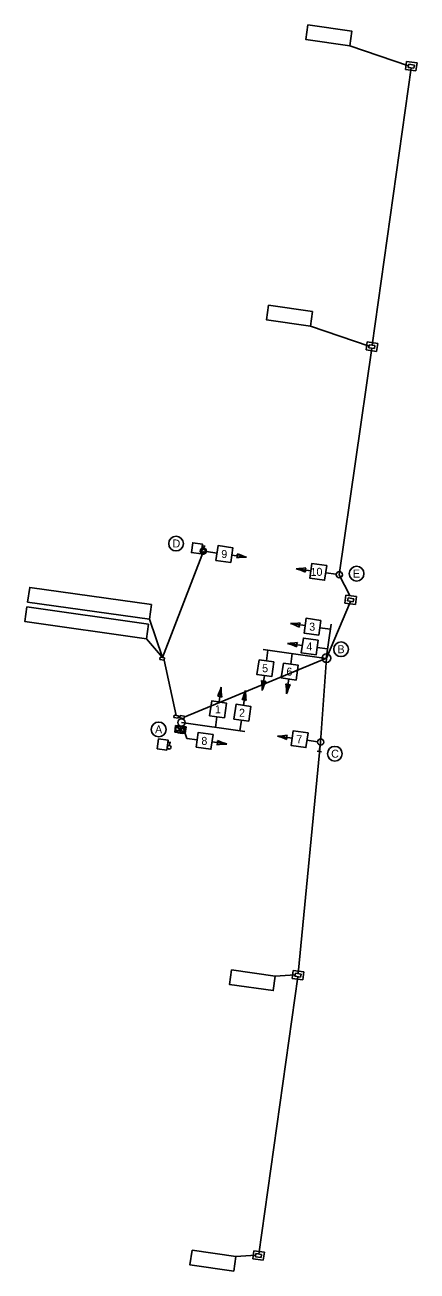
# Model space of a CAD drawing. Extents: x 993729 to 994927, y 1984823 to 1986420.
# Drawn here: x 993729 to 993889, y 1985201 to 1985707 of the extents above; entities that cross this region are included whole.
import ezdxf

# ---------------------------------------------------------------- set-up
doc = ezdxf.new("R2010")
doc.units = 0
for name, color, linetype in [('EX_BREAKLINE_PT_SYM', 7, 'Continuous'), ('EX_FLAG_POLE', 7, 'Continuous'), ('EX_GAS_UTILITIES', 7, 'Continuous'), ('EX_LANDSCAPING', 7, 'Continuous'), ('EX_MSC_PT_SYM', 7, 'Continuous'), ('EX_SANITARY_SEWER', 7, 'Continuous'), ('EX_UTILITY_MARKER', 7, 'Continuous')]:
    doc.layers.add(name, color=color, linetype=linetype)

msp = doc.modelspace()

# ---------------------------------------------------------------- linework, layer by layer
at = {"layer": 'EX_BREAKLINE_PT_SYM'}
for p, q in [((993802.89, 1985493.48), (993807.19, 1985492.87)), ((993813.2, 1985492.06), (993819.18, 1985491.22)), ((993845.41, 1985485.66), (993839.43, 1985486.49)), ((993855.72, 1985484.24), (993851.42, 1985484.84)), ((993843.03, 1985463.38), (993837.05, 1985464.23)), ((993853.34, 1985461.94), (993849.04, 1985462.55)), ((993841.9, 1985455.34), (993835.92, 1985456.19)), ((993827.91, 1985453.4), (993827.29, 1985449.1)), ((993837.81, 1985452.03), (993837.2, 1985447.72)), ((993852.21, 1985453.9), (993847.91, 1985454.51)), ((993826.46, 1985443.09), (993825.62, 1985437.11)), ((993836.37, 1985441.72), (993835.52, 1985435.74)), ((993808.02, 1985432.39), (993808.87, 1985438.37)), ((993817.93, 1985431.01), (993818.77, 1985436.99)), ((993806.58, 1985422.08), (993807.19, 1985426.38)), ((993794.87, 1985417.61), (993793.27, 1985422.38)), ((993816.48, 1985420.7), (993817.1, 1985425.01)), ((993794.87, 1985417.61), (993799.17, 1985417)), ((993805.18, 1985416.17), (993811.16, 1985415.32)), ((993837.8, 1985417.69), (993831.82, 1985418.54)), ((993848.11, 1985416.25), (993843.81, 1985416.86))]:
    msp.add_line(p, q, dxfattribs=at)
for points in [[(993806.77, 1985489.89), (993807.61, 1985495.89), (993813.62, 1985495.05), (993812.78, 1985489.05)], [(993851.84, 1985487.83), (993850.99, 1985481.82), (993844.99, 1985482.66), (993845.83, 1985488.67)], [(993849.46, 1985465.54), (993848.61, 1985459.54), (993842.61, 1985460.39), (993843.46, 1985466.39)], [(993848.33, 1985457.49), (993847.48, 1985451.49), (993841.48, 1985452.34), (993842.33, 1985458.35)], [(993824.31, 1985449.52), (993830.31, 1985448.67), (993829.46, 1985442.67), (993823.45, 1985443.52)], [(993834.21, 1985448.15), (993840.22, 1985447.29), (993839.36, 1985441.29), (993833.36, 1985442.14)], [(993810.18, 1985425.96), (993804.17, 1985426.81), (993805.03, 1985432.81), (993811.03, 1985431.96)], [(993820.08, 1985424.58), (993814.08, 1985425.43), (993814.93, 1985431.44), (993820.94, 1985430.58)], [(993844.23, 1985419.85), (993843.38, 1985413.84), (993837.38, 1985414.69), (993838.23, 1985420.7)], [(993798.75, 1985414.01), (993799.6, 1985420.02), (993805.6, 1985419.17), (993804.75, 1985413.16)]]:
    msp.add_lwpolyline(points, close=True, dxfattribs=at)
for centre, radius, start, end in [((993813.97, 1985491.95), 1.63, 320.1833, 23.8779), ((993827.59, 1985519.47), 29.47, 245.6842, 253.4223), ((993819.51, 1985461.75), 29.47, 90.6389, 98.377), ((993839.1, 1985515.97), 29.47, 270.6389, 278.377), ((993831.02, 1985458.25), 29.47, 65.6842, 73.4223), ((993844.64, 1985485.76), 1.63, 140.1833, 203.8779), ((993836.78, 1985493.7), 29.47, 270.5231, 278.2612), ((993828.59, 1985436), 29.47, 65.5684, 73.3065), ((993842.27, 1985463.49), 1.63, 140.0675, 203.7621), ((993835.65, 1985485.66), 29.47, 270.5231, 278.2612), ((993827.45, 1985427.96), 29.47, 65.5684, 73.3065), ((993841.13, 1985455.45), 1.63, 140.0675, 203.7621), ((993796.14, 1985436.84), 29.47, 0.5231, 8.2612), ((993826.36, 1985442.33), 1.63, 230.0675, 293.7621), ((993780.64, 1985446.83), 29.47, 335.5684, 343.3065), ((993838.34, 1985438.64), 29.47, 180.5231, 188.2612), ((993790.55, 1985445.46), 29.47, 335.5684, 343.3065), ((993848.25, 1985437.26), 29.47, 180.5231, 188.2612), ((993853.84, 1985428.65), 29.47, 155.5684, 163.3065), ((993806.05, 1985435.47), 29.47, 0.5231, 8.2612), ((993836.26, 1985440.95), 1.63, 230.0675, 293.7621), ((993863.75, 1985427.27), 29.47, 155.5684, 163.3065), ((993808.13, 1985433.15), 1.63, 50.0675, 113.7621), ((993818.03, 1985431.78), 1.63, 50.0675, 113.7621), ((993805.94, 1985416.06), 1.63, 320.0649, 23.7595), ((993819.62, 1985443.55), 29.47, 245.5658, 253.3039), ((993831.55, 1985448.01), 29.47, 270.5289, 278.267), ((993823.36, 1985390.31), 29.47, 65.5741, 73.3122), ((993837.04, 1985417.8), 1.63, 140.0732, 203.7679), ((993811.42, 1985385.85), 29.47, 90.5205, 98.2586)]:
    msp.add_arc(centre, radius, start, end, dxfattribs=at)
at = {"layer": 'EX_FLAG_POLE'}
for p, q in [((993861.19, 1985698.9), (993885.08, 1985690.75)), ((993870.31, 1985577.33), (993886.15, 1985689.95)), ((993845.18, 1985585.02), (993869.07, 1985576.87)), ((993870.13, 1985576.07), (993856.96, 1985484.06)), ((993801.65, 1985493.65), (993784.98, 1985450.43)), ((993861.3, 1985475.56), (993856.96, 1985484.06)), ((993851.69, 1985450.18), (993861.48, 1985473.24)), ((993779.67, 1985466.01), (993784.98, 1985450.43)), ((993778.55, 1985458.09), (993784.98, 1985450.43)), ((993785.71, 1985449.4), (993790.65, 1985426.89)), ((993793.86, 1985426.18), (993851.69, 1985450.18)), ((993851.69, 1985450.18), (993849.35, 1985416.07)), ((993849.35, 1985416.07), (993840.22, 1985322.07)), ((993840.04, 1985320.81), (993824.21, 1985208.19)), ((993830.88, 1985321.09), (993838.98, 1985321.6)), ((993814.87, 1985207.21), (993822.96, 1985207.72))]:
    msp.add_line(p, q, dxfattribs=at)
at = {"layer": 'EX_GAS_UTILITIES'}
for points in [[(993800.73, 1985492.52), (993796.77, 1985493.07), (993797.33, 1985497.03), (993801.29, 1985496.48)], [(993786.82, 1985412.85), (993782.86, 1985413.4), (993783.42, 1985417.36), (993787.38, 1985416.81)]]:
    msp.add_lwpolyline(points, close=True, dxfattribs=at)
at = {"layer": 'EX_LANDSCAPING'}
for p, q in [((993883.86, 1985689.27), (993884.32, 1985692.5)), ((993888.15, 1985688.66), (993883.86, 1985689.27)), ((993884.32, 1985692.5), (993888.61, 1985691.9)), ((993884.99, 1985690.12), (993885.17, 1985691.37)), ((993887.3, 1985689.79), (993884.99, 1985690.12)), ((993885.17, 1985691.37), (993887.48, 1985691.05)), ((993887.48, 1985691.05), (993887.3, 1985689.79)), ((993888.61, 1985691.9), (993888.15, 1985688.66)), ((993867.85, 1985575.39), (993868.3, 1985578.62)), ((993868.3, 1985578.62), (993872.59, 1985578.02)), ((993868.98, 1985576.24), (993869.15, 1985577.49)), ((993869.15, 1985577.49), (993871.46, 1985577.17)), ((993872.59, 1985578.02), (993872.14, 1985574.78)), ((993872.14, 1985574.78), (993867.85, 1985575.39)), ((993871.29, 1985575.91), (993868.98, 1985576.24)), ((993871.46, 1985577.17), (993871.29, 1985575.91)), ((993802.37, 1985495.64), (993801.5, 1985495.76)), ((993801.75, 1985494.39), (993801.94, 1985495.7)), ((993859.65, 1985475.79), (993859.19, 1985472.55)), ((993859.19, 1985472.55), (993863.49, 1985471.95)), ((993863.94, 1985475.19), (993859.65, 1985475.79)), ((993860.5, 1985474.66), (993860.32, 1985473.4)), ((993860.32, 1985473.4), (993862.63, 1985473.08)), ((993862.81, 1985474.34), (993860.5, 1985474.66)), ((993862.63, 1985473.08), (993862.81, 1985474.34)), ((993863.49, 1985471.95), (993863.94, 1985475.19)), ((993784.11, 1985450.55), (993783.98, 1985449.64)), ((993783.98, 1985449.64), (993785.71, 1985449.4)), ((993785.84, 1985450.31), (993784.11, 1985450.55)), ((993785.71, 1985449.4), (993785.84, 1985450.31)), ((993789.78, 1985427.01), (993789.65, 1985426.1)), ((993789.65, 1985426.1), (993791.39, 1985425.86)), ((993791.51, 1985426.77), (993789.78, 1985427.01)), ((993791.39, 1985425.86), (993791.51, 1985426.77)), ((993792.19, 1985426.88), (993792.06, 1985425.96)), ((993792.06, 1985425.96), (993793.79, 1985425.72)), ((993793.92, 1985426.63), (993792.19, 1985426.88)), ((993793.79, 1985425.72), (993793.92, 1985426.63)), ((993792.47, 1985422.31), (993792.11, 1985419.7)), ((993788.46, 1985415.97), (993787.59, 1985416.09)), ((993787.84, 1985414.72), (993788.03, 1985416.03)), ((993791.24, 1985419.82), (993792.97, 1985419.58)), ((993847.95, 1985412.35), (993849.67, 1985412.1)), ((993849.18, 1985414.84), (993848.81, 1985412.23)), ((993838.22, 1985323.36), (993837.76, 1985320.12)), ((993837.76, 1985320.12), (993842.05, 1985319.52)), ((993842.51, 1985322.76), (993838.22, 1985323.36)), ((993839.07, 1985322.23), (993838.89, 1985320.97)), ((993838.89, 1985320.97), (993841.2, 1985320.65)), ((993841.38, 1985321.9), (993839.07, 1985322.23)), ((993841.2, 1985320.65), (993841.38, 1985321.9)), ((993842.05, 1985319.52), (993842.51, 1985322.76)), ((993822.2, 1985209.48), (993821.75, 1985206.24)), ((993826.49, 1985208.88), (993822.2, 1985209.48)), ((993823.05, 1985208.35), (993822.88, 1985207.09)), ((993825.36, 1985208.02), (993823.05, 1985208.35)), ((993826.04, 1985205.64), (993826.49, 1985208.88)), ((993821.75, 1985206.24), (993826.04, 1985205.64)), ((993822.88, 1985207.09), (993825.19, 1985206.77)), ((993825.19, 1985206.77), (993825.36, 1985208.02))]:
    msp.add_line(p, q, dxfattribs=at)
at = {"layer": 'EX_MSC_PT_SYM'}
for p, q in [((993851.67, 1985450.06), (993853.62, 1985463.92)), ((993851.67, 1985450.06), (993825.92, 1985453.68)), ((993792.72, 1985424.04), (993818.47, 1985420.42))]:
    msp.add_line(p, q, dxfattribs=at)
for centre, radius in [((993790.56, 1985496.71), 3), ((993801.65, 1985493.65), 1.25), ((993801.65, 1985493.65), 0.75), ((993863.97, 1985484.51), 3), ((993856.96, 1985484.06), 1.25), ((993857.67, 1985453.79), 3), ((993851.69, 1985450.18), 1.75), ((993783.47, 1985421.22), 3), ((993792.72, 1985424.04), 1.5), ((993849.35, 1985416.07), 1.25), ((993787.74, 1985413.98), 0.75), ((993855.12, 1985411.36), 3)]:
    msp.add_circle(centre, radius, dxfattribs=at)
at = {"layer": 'EX_SANITARY_SEWER'}
for p, q in [((993790.37, 1985422.86), (993789.98, 1985420.15)), ((993790.65, 1985422.49), (993790.36, 1985420.43)), ((993790.36, 1985420.43), (993794.28, 1985421.97)), ((993794.65, 1985422.26), (993790.37, 1985422.86)), ((993794.28, 1985421.98), (993790.65, 1985422.49)), ((993793.97, 1985419.92), (993790.65, 1985422.49)), ((993794.28, 1985421.98), (993793.99, 1985419.92)), ((993794.65, 1985422.26), (993794.27, 1985419.54)), ((993794.27, 1985419.54), (993789.98, 1985420.15)), ((993793.99, 1985419.92), (993790.36, 1985420.43))]:
    msp.add_line(p, q, dxfattribs=at)
at = {"layer": 'EX_UTILITY_MARKER'}
for points in [[(993844.2, 1985707.35), (993843.37, 1985701.4), (993861.19, 1985698.9), (993862.03, 1985704.84)], [(993828.19, 1985593.47), (993827.35, 1985587.53), (993845.18, 1985585.02), (993846.01, 1985590.96)], [(993780.5, 1985471.95), (993730.99, 1985478.91), (993730.15, 1985472.97), (993779.67, 1985466.01)], [(993779.39, 1985464.03), (993729.88, 1985470.99), (993729.04, 1985465.05), (993778.55, 1985458.09)], [(993813.06, 1985323.59), (993812.22, 1985317.65), (993830.05, 1985315.15), (993830.88, 1985321.09)], [(993797.04, 1985209.71), (993796.21, 1985203.77), (993814.03, 1985201.27), (993814.87, 1985207.21)]]:
    msp.add_lwpolyline(points, close=True, dxfattribs=at)

# ---------------------------------------------------------------- texts
at = {"layer": 'EX_BREAKLINE_PT_SYM'}
for s, p in [('9', (993808.97, 1985490.83)), ('10', (993845.26, 1985483.56)), ('3', (993844.73, 1985461.32)), ('4', (993843.59, 1985453.27)), ('5', (993825.58, 1985444.45)), ('6', (993835.47, 1985443.07)), ('1', (993806.37, 1985427.75)), ('2', (993816.18, 1985426.36)), ('8', (993800.86, 1985414.94)), ('7', (993839.49, 1985415.62))]:
    msp.add_text(s, height=3.25, rotation=0.8934, dxfattribs=at).set_placement(p)
at = {"layer": 'EX_MSC_PT_SYM'}
for s, p in [('D', (993789.08, 1985495.14)), ('E', (993862.46, 1985482.94)), ('B', (993856.17, 1985452.21)), ('A', (993781.99, 1985419.65)), ('C', (993853.62, 1985409.78))]:
    msp.add_text(s, height=3.25, rotation=359.1959, dxfattribs=at).set_placement(p)

doc.saveas('drawing.dxf')
